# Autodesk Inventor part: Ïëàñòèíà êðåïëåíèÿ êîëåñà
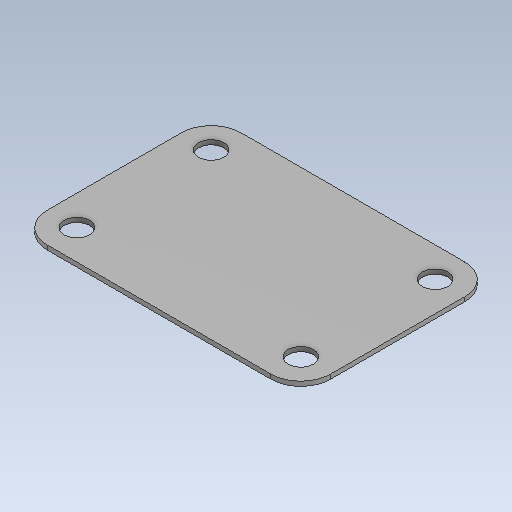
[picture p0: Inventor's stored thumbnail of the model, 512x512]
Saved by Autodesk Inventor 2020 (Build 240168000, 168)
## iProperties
Created: 1900-01
Part Number: Ïëàñòèíà êðåïëåíèÿ êîëåñà
Material: Générique
Document SubType Name: Modeling
Designer: bruno
Density: 1 g/cm^3
Appearance: Par défaut
Author: bruno
Revision Number: ANYUNSPECIFIED
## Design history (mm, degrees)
feature "Base1"
node "Solide1"
